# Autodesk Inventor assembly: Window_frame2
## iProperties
Shininess: 64.0
Length Units: 11269
Angle Units: 11279
Time Units: 11290
Mass Units: 11283
Length Display Precision: 3
Angle Display Precision: 2
Compacted: True
Created: 2003-02
Part Number: Window_frame2
Document SubType Name: Assembly
Designer: hofer_a
Density: 0.0
Volumn: 0.0
Area: 0.0
PropertySet Name: Model Information
Control State: 0
Master: False
Checked Out: False
Author: hofer_a
